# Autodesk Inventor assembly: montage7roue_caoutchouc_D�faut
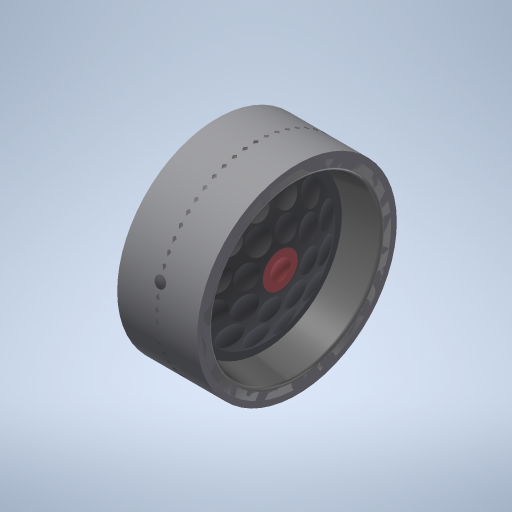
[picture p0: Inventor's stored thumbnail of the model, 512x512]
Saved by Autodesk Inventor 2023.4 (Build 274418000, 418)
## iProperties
Created: 2011-01
Part Number: montage7roue_caoutchouc_D�faut
Document SubType Name: Assembly
Designer: eric
Mass: 3043.31 g
Surface Area: 5165.36 cm^2
Volume: 3043.31 cm^3
Density: 1 g/cm^3
Author: eric
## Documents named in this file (29)
- C:\Users\bruno\Documents\1-Cours-2024-25\TSsI\7-Dynamique\chariot de golf\chariot_de_golf\chariot_de_golf_trolem\montage7roue_caoutchouc_Defaut.iam
- C:\Users\bruno\Documents\1-Cours-2024-25\TSsI\7-Dynamique\chariot de golf\chariot_de_golf\chariot_de_golf_trolem\7pneu_caoutchouc_Defaut.ipt
- C:\Users\bruno\Documents\1-Cours-2024-25\TSsI\7-Dynamique\chariot de golf\chariot_de_golf\chariot_de_golf_trolem\Rondelle_20x40x1_Defaut.ipt
- C:\Users\bruno\Documents\1-Cours-2024-25\TSsI\7-Dynamique\chariot de golf\chariot_de_golf\chariot_de_golf_trolem\8jante_bombee_Defaut.ipt
- C:\Users\bruno\Documents\1-Cours-2024-25\TSsI\7-Dynamique\chariot de golf\chariot_de_golf\chariot_de_golf_trolem\HF_20_26_16 _Defaut.iam
- C:\Users\bruno\Documents\1-Cours-2024-25\TSsI\7-Dynamique\chariot de golf\chariot_de_golf\chariot_de_golf_trolem\62goupille_epingle_Defaut.ipt
- C:\Users\bruno\Documents\1-Cours-2024-25\TSsI\7-Dynamique\chariot de golf\chariot_de_golf\chariot_de_golf_trolem\entretoise1_Defaut.ipt
- C:\Users\bruno\Documents\1-Cours-2024-25\TSsI\7-Dynamique\chariot de golf\chariot_de_golf\chariot_de_golf_trolem\Ecrou_H_M6_Defaut.ipt
- C:\Users\bruno\Documents\1-Cours-2024-25\TSsI\7-Dynamique\chariot de golf\chariot_de_golf\chariot_de_golf_trolem\anneauext18_Defaut.ipt
- C:\Users\bruno\Documents\1-Cours-2024-25\TSsI\7-Dynamique\chariot de golf\chariot_de_golf\chariot_de_golf_trolem\Bague_insert1_Defaut.ipt
- C:\Users\bruno\Documents\1-Cours-2024-25\TSsI\7-Dynamique\chariot de golf\chariot_de_golf\chariot_de_golf_trolem\8Vis_ M 6 x 40.ipt
- C:\Users\bruno\Documents\1-Cours-2024-25\TSsI\7-Dynamique\chariot de golf\chariot_de_golf\chariot_de_golf_trolem\Rondelle_20x32x1_Defaut.ipt
- C:\Users\bruno\Documents\1-Cours-2024-25\TSsI\7-Dynamique\chariot de golf\chariot_de_golf\chariot_de_golf_trolem\8bouchon_Defaut.ipt
- C:\Users\bruno\Documents\1-Cours-2024-25\TSsI\7-Dynamique\chariot de golf\chariot_de_golf\chariot_de_golf_trolem\Coussinet_cylindrique66_Defaut.ipt
- C:\Users\bruno\Documents\1-Cours-2024-25\TSsI\7-Dynamique\chariot de golf\chariot_de_golf\chariot_de_golf_trolem\cylindre_roue_simul.ipt
- D:\Cours\Inventor salle SI\chariot_de_golf_2008\chariot_de_golf_trolem\7pneu_caoutchouc_Defaut.ipt
- D:\Cours\Inventor salle SI\chariot_de_golf_2008\chariot_de_golf_trolem\Rondelle_20x40x1_Defaut.ipt
- D:\Cours\Inventor salle SI\chariot_de_golf_2008\chariot_de_golf_trolem\8jante_bombee_Defaut.ipt
- D:\Cours\Inventor salle SI\chariot_de_golf_2008\chariot_de_golf_trolem\HF_20_26_16 _Defaut.iam
- D:\Cours\Inventor salle SI\chariot_de_golf_2008\chariot_de_golf_trolem\62goupille_epingle_Defaut.ipt
- D:\Cours\Inventor salle SI\chariot_de_golf_2008\chariot_de_golf_trolem\entretoise1_Defaut.ipt
- D:\Cours\Inventor salle SI\chariot_de_golf_2008\chariot_de_golf_trolem\Ecrou_H_M6_Defaut.ipt
- D:\Cours\Inventor salle SI\chariot_de_golf_2008\chariot_de_golf_trolem\anneauext18_Defaut.ipt
- D:\Cours\Inventor salle SI\chariot_de_golf_2008\chariot_de_golf_trolem\Bague_insert1_Defaut.ipt
- D:\Cours\Inventor salle SI\chariot_de_golf_2008\chariot_de_golf_trolem\8Vis_ M 6 x 40.ipt
- D:\Cours\Inventor salle SI\chariot_de_golf_2008\chariot_de_golf_trolem\Rondelle_20x32x1_Defaut.ipt
- D:\Cours\Inventor salle SI\chariot_de_golf_2008\chariot_de_golf_trolem\8bouchon_Defaut.ipt
- D:\Cours\Inventor salle SI\chariot_de_golf_2008\chariot_de_golf_trolem\Coussinet_cylindrique66_Defaut.ipt
- D:\Cours\Inventor salle SI\chariot_de_golf_2008\chariot_de_golf_trolem\cylindre_roue_simul.ipt
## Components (17 placed, 14 different names)
1. 7pneu_caoutchouc_Defaut:1 — Affleurement:1
2. Rondelle_20x40x1_Defaut:1
3. 8jante_bombee_Defaut:1
4. HF_20_26_16 _Defaut:1 [sub-assembly]
5. 62goupille_epingle_Defaut:1
6. entretoise1_Defaut:1
7. Ecrou_H_M6_Defaut:1
8. anneauext18_Defaut:1
9. Bague_insert1_Defaut:1
10. 8Vis_ M 6 x 40:1
11. Rondelle_20x32x1_Defaut:1
12. Ecrou_H_M6_Defaut:2
13. 8Vis_ M 6 x 40:2
14. 8bouchon_Defaut:1
15. Coussinet_cylindrique66_Defaut:1
16. anneauext18_Defaut:2
17. cylindre_roue_simul:1 — Affleurement:1
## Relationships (1: Flush 1)
- Affleurement:1 [Flush]: 7pneu_caoutchouc_Defaut:1 ↔ cylindre_roue_simul:1
